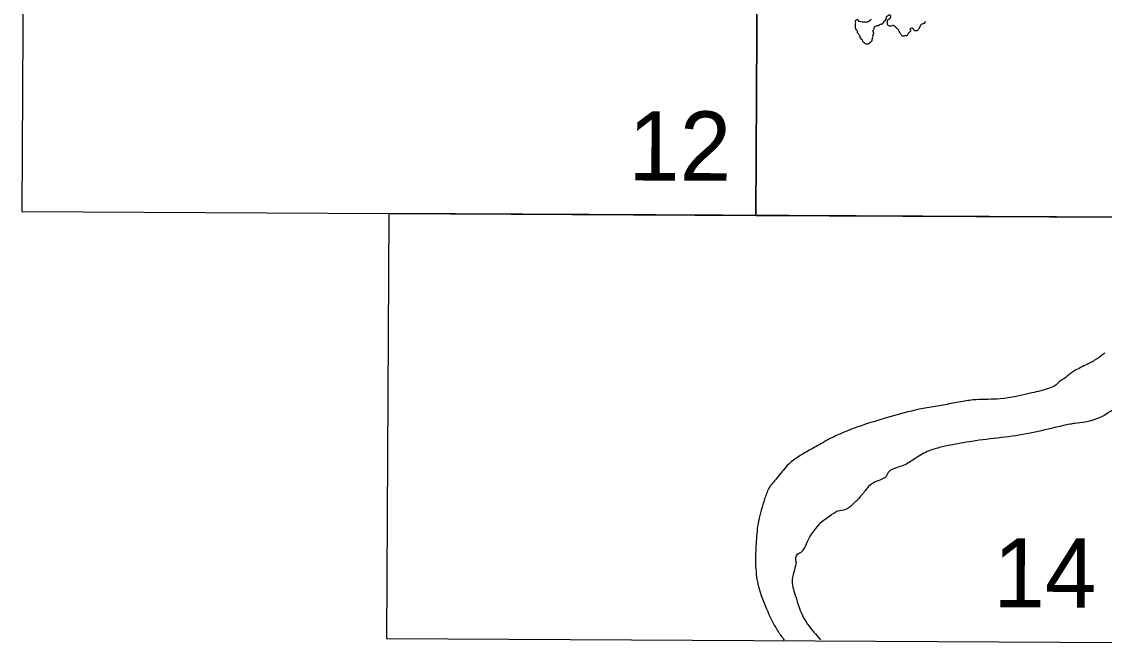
# Model space of a CAD drawing. Extents: x 3161514 to 3199414, y 831166 to 856601.
# Drawn here: x 3185783 to 3187612, y 833461 to 834510 of the extents above; entities that cross this region are included whole.
import ezdxf

# ---------------------------------------------------------------- set-up
doc = ezdxf.new("R2010")
doc.units = 0
doc.layers.add('V-ANNO-NPLT', color=7, linetype='Continuous')

msp = doc.modelspace()

# ---------------------------------------------------------------- linework, layer by layer
at = {"layer": 'V-ANNO-NPLT'}
for points in [[(3185783.1, 834189), (3187023.2, 834182.2), (3187026.9, 834900.5), (3185787.4, 834907.4), (3185783.1, 834189)], [(3187023.2, 834182.2), (3188263.4, 834176.4), (3188266.4, 834894.7), (3187026.9, 834900.5), (3187023.2, 834182.2)], [(3186399.2, 833467.1), (3187640, 833460.8), (3187643.3, 834179.1), (3186403.2, 834185.5), (3186399.2, 833467.1)]]:
    msp.add_lwpolyline(points, dxfattribs=at)
for points in [[(3187283.5, 834497.9), (3187284.2, 834493.7), (3187282.8, 834492.1), (3187282.3, 834491.4), (3187280.8, 834490.3), (3187280.7, 834489.5), (3187278.7, 834486.6), (3187278.8, 834486.2), (3187277.5, 834485.8), (3187271.1, 834485.4), (3187267.8, 834488.6), (3187266.1, 834491.3), (3187264.2, 834495.4), (3187260.5, 834499.2), (3187258.8, 834501.1), (3187256.2, 834503.1), (3187250.1, 834502.1), (3187248.7, 834502.3), (3187246.9, 834503.2), (3187246.2, 834503.9), (3187245.5, 834506.9), (3187246.1, 834512.6), (3187247.5, 834513.8), (3187248.4, 834514), (3187248.6, 834514.6), (3187249.2, 834515), (3187249.6, 834515.9), (3187250.3, 834516.4), (3187250.3, 834520.4), (3187249.8, 834520.6), (3187246.3, 834519.7), (3187245.7, 834519.2), (3187243.5, 834518.1), (3187242.9, 834516.5), (3187243.1, 834515.3), (3187242.7, 834514.7), (3187242.8, 834513.8), (3187242.4, 834512.4), (3187241.7, 834512.1), (3187241.6, 834511.4), (3187240.6, 834511), (3187238.8, 834508.9), (3187238.6, 834507.9), (3187237.8, 834507.5), (3187237.4, 834506.6), (3187233.1, 834504.8), (3187230.9, 834503.5), (3187224.9, 834501.6), (3187224.1, 834501.2), (3187222.8, 834500.2), (3187222.2, 834498), (3187222.3, 834496.9), (3187221, 834495), (3187221.7, 834488.9), (3187221, 834488.3), (3187220.6, 834484.7), (3187219.7, 834483.1), (3187220, 834480.8), (3187219.3, 834480), (3187219.5, 834478.6), (3187218.7, 834476.8), (3187217.7, 834475.6), (3187215.7, 834474.4), (3187215.1, 834473.8), (3187213.6, 834472.2), (3187211.8, 834471.6), (3187209.5, 834471.8), (3187207.1, 834473.1), (3187206.2, 834474.2), (3187204.5, 834475.5), (3187204.1, 834476.5), (3187199.5, 834483.6), (3187198.4, 834486.3), (3187197.8, 834486.8), (3187196.7, 834489.3), (3187196, 834489.5), (3187195.1, 834491.1), (3187193.9, 834495.1), (3187193.2, 834495.8), (3187191.2, 834504.7), (3187191.2, 834505.4), (3187191.7, 834506.8), (3187191.6, 834509), (3187192.2, 834512), (3187193.5, 834513.1), (3187195.2, 834513.3), (3187196.3, 834511.1), (3187197.3, 834510.6), (3187198.4, 834510.6), (3187202.5, 834509.2), (3187206.4, 834509.5), (3187206.9, 834509.3), (3187209.7, 834509.3), (3187213.5, 834510.2), (3187216, 834512.4), (3187218, 834513.3), (3187217.9, 834514.2)], [(3187309.2, 834509.8), (3187307.5, 834506.9), (3187302.5, 834505), (3187300.5, 834502.6), (3187299.3, 834499.8), (3187298.1, 834496.9), (3187296.1, 834494.8), (3187293.7, 834494.1), (3187291.2, 834494.4), (3187290.2, 834496.6), (3187287.4, 834498.5), (3187286.6, 834498.6), (3187283.5, 834497.9)], [(3187612.5, 833949.5), (3187599.4, 833940), (3187582.5, 833930.5), (3187561.2, 833919.6), (3187554.6, 833915.2), (3187543.6, 833906.4), (3187537.7, 833902.8), (3187529.6, 833895.5), (3187519.4, 833890.4), (3187489.3, 833882.4), (3187435.7, 833872.2), (3187395.4, 833870.9), (3187372.7, 833868), (3187346.3, 833863)], [(3187742.4, 833945.2), (3187726.2, 833926.5), (3187708.5, 833907.4), (3187682.8, 833888.4), (3187660.1, 833875.3), (3187643.2, 833865.1), (3187616.7, 833847.5), (3187579.3, 833833), (3187561.7, 833830.8), (3187553.6, 833829.4), (3187486.2, 833814.1), (3187437.8, 833806.9), (3187387.9, 833800.5), (3187351.2, 833794)], [(3187346.3, 833863), (3187292.4, 833853.2), (3187243.2, 833840.1), (3187201.4, 833827), (3187153, 833807.3), (3187128, 833793.5)], [(3187128, 833793.5), (3187106.3, 833781.4), (3187076.2, 833759.5), (3187057.8, 833737.5), (3187045.3, 833721.4), (3187038, 833703.1), (3187027.6, 833665.7), (3187023.8, 833631.9), (3187022.3, 833598.2)], [(3187351.2, 833794), (3187330.3, 833789.2), (3187318.6, 833785.6), (3187295.8, 833773.9), (3187277.5, 833762.2), (3187254.7, 833753.5), (3187246.6, 833747.6), (3187244.4, 833743.3), (3187227.5, 833733), (3187213.6, 833724.3), (3187207.7, 833716.9), (3187195.2, 833702.3)], [(3187091.2, 833596.5), (3187093.4, 833609.7), (3187097.1, 833611.9), (3187100.8, 833614.1), (3187105.2, 833620), (3187111.8, 833634.6), (3187124.3, 833653), (3187136.1, 833666.1), (3187147.8, 833674.2), (3187161.8, 833682.9), (3187175, 833685.8), (3187183.1, 833690.9), (3187188.9, 833696.1), (3187195.2, 833702.3)], [(3187022.3, 833598.4), (3187025.8, 833563), (3187041.1, 833517.4), (3187059.3, 833481.4), (3187070.9, 833464.7)], [(3187091.3, 833597.2), (3187088.2, 833583.3), (3187084.5, 833567.2), (3187089.6, 833540.8), (3187101.9, 833506.2), (3187120.9, 833478.3), (3187132.4, 833465.2)]]:
    msp.add_spline(points, degree=3, dxfattribs=at)

# ---------------------------------------------------------------- texts
for s, p in [('12', (3186807.4, 834241.4)), ('14', (3187424.1, 833520))]:
    msp.add_text(s, height=117, rotation=359.8417, dxfattribs=at).set_placement(p)

doc.saveas('drawing.dxf')
